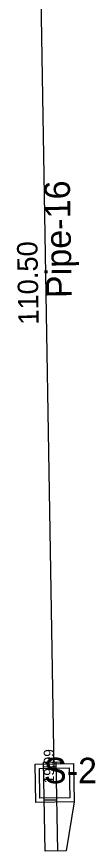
# Model space of a CAD drawing. Extents: x 925371 to 925937, y 853654 to 858024.
# Drawn here: x 925850.5 to 925859.7, y 853701.2 to 853799.4 of the extents above; entities that cross this region are included whole.
import ezdxf

# ---------------------------------------------------------------- set-up
doc = ezdxf.new("R2010")
doc.units = 0
for name, color, linetype in [('GPKDrBack_dp', 7, 'Continuous'), ('GPKDrBottom_dp', 7, 'Continuous'), ('GPKDrCellIns_dp', 7, 'Continuous'), ('GPKDrCentroid_dp', 7, 'Continuous'), ('GPKDrFront_dp', 7, 'Continuous'), ('GPKDrPipe_dp', 7, 'Continuous'), ('GPKDrPipeCir_dp', 7, 'Continuous'), ('InletBottomP', 7, 'Continuous'), ('InletCurb', 7, 'Continuous'), ('NonPlottingEle_dp', 7, 'Continuous'), ('PipeCulvert', 7, 'Continuous')]:
    doc.layers.add(name, color=color, linetype=linetype)

msp = doc.modelspace()

# ---------------------------------------------------------------- linework, layer by layer
at = {"layer": 'GPKDrBack_dp'}
for p, q in [((925856.65, 853709.292), (925856.65, 853709.292)), ((925857.149, 853709.3), (925857.149, 853709.3))]:
    msp.add_line(p, q, dxfattribs=at)
at = {"layer": 'GPKDrBottom_dp'}
for p, q in [((925853.12, 853710.982), (925853.12, 853710.982)), ((925853.12, 853710.982), (925853.12, 853710.982)), ((925854.87, 853711.012), (925854.87, 853711.012)), ((925854.87, 853711.012), (925854.87, 853711.012)), ((925856.62, 853711.042), (925856.62, 853711.042)), ((925856.62, 853711.041), (925856.62, 853711.041)), ((925853.15, 853709.232), (925853.15, 853709.232)), ((925853.15, 853709.232), (925853.15, 853709.232)), ((925854.9, 853709.262), (925854.9, 853709.262)), ((925854.9, 853709.262), (925854.9, 853709.262)), ((925856.65, 853709.292), (925856.65, 853709.292)), ((925856.65, 853709.292), (925856.65, 853709.292)), ((925853.18, 853707.483), (925853.18, 853707.483)), ((925853.18, 853707.482), (925853.18, 853707.482)), ((925854.93, 853707.512), (925854.93, 853707.512)), ((925854.93, 853707.512), (925854.93, 853707.512)), ((925856.679, 853707.542), (925856.679, 853707.542)), ((925856.679, 853707.542), (925856.679, 853707.542))]:
    msp.add_line(p, q, dxfattribs=at)
at = {"layer": 'GPKDrCellIns_dp'}
for p, q in [((925853.65, 853709.241), (925853.65, 853709.241)), ((925854.9, 853709.262), (925854.9, 853709.262))]:
    msp.add_line(p, q, dxfattribs=at)
at = {"layer": 'GPKDrCentroid_dp'}
msp.add_line((925854.9, 853709.262), (925854.9, 853709.262), dxfattribs=at)
at = {"layer": 'GPKDrFront_dp'}
for p, q in [((925853.15, 853709.232), (925853.15, 853709.232)), ((925853.65, 853709.241), (925853.65, 853709.241))]:
    msp.add_line(p, q, dxfattribs=at)
at = {"layer": 'GPKDrPipe_dp'}
for p, q in [((925854.87, 853711.012), (925854.87, 853711.012)), ((925854.87, 853711.012), (925854.87, 853711.012)), ((925853.15, 853709.232), (925853.15, 853709.232)), ((925853.15, 853709.232), (925853.15, 853709.232)), ((925856.65, 853709.292), (925856.65, 853709.292)), ((925856.65, 853709.292), (925856.65, 853709.292)), ((925854.93, 853707.512), (925854.93, 853707.512)), ((925854.93, 853707.512), (925854.93, 853707.512))]:
    msp.add_line(p, q, dxfattribs=at)
at = {"layer": 'GPKDrPipeCir_dp'}
msp.add_lwpolyline([(925853.18, 853707.482), (925853.12, 853710.982), (925856.62, 853711.041), (925856.679, 853707.542)], close=True, dxfattribs=at)
at = {"layer": 'InletBottomP'}
for points in [[(925857.111, 853711.55), (925857.188, 853707.051), (925852.688, 853706.974), (925852.612, 853711.474)], [(925853.12, 853710.982), (925856.62, 853711.042), (925856.679, 853707.542), (925853.18, 853707.483)]]:
    msp.add_lwpolyline(points, close=True, dxfattribs=at)
at = {"layer": 'InletCurb'}
for p, q in [((925853.607, 853711.74), (925855.607, 853711.774)), ((925853.786, 853701.242), (925853.607, 853711.74)), ((925853.617, 853711.189), (925855.117, 853711.215)), ((925855.286, 853701.267), (925855.107, 853711.766)), ((925855.607, 853711.774), (925855.611, 853711.524)), ((925855.611, 853711.524), (925857.111, 853711.55)), ((925857.111, 853711.55), (925857.188, 853707.051)), ((925853.683, 853707.283), (925855.183, 853707.308)), ((925857.188, 853707.051), (925856.286, 853701.284)), ((925856.286, 853701.284), (925853.786, 853701.242))]:
    msp.add_line(p, q, dxfattribs=at)
at = {"layer": 'PipeCulvert'}
msp.add_line((925854.87, 853711.012), (925852.991, 853821.496), dxfattribs=at)

# ---------------------------------------------------------------- texts
at = {"layer": 'NonPlottingEle_dp'}
for s, height, rotation, p in [('Pipe-16', 3, 90.97411, (925856.93, 853766.305)), ('110.50', 2.4, 90.97411, (925853.046, 853763.166)), ('19.99', 1.2, 90, (925854.834, 853709.234))]:
    msp.add_text(s, height=height, rotation=rotation, dxfattribs=at).set_placement(p)
msp.add_text('S-2', height=3, dxfattribs=at).set_placement((925853.65, 853709.241))

doc.saveas('drawing.dxf')
